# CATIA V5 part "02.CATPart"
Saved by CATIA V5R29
Part number: 02
Bounding box of the stored display mesh (mm): x -24 to 24, y -16 to 0, z 0 to 16
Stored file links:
  F:\1-Dersler\2-BAHAR\Bilgisayar Destekli Mühendislik Tasarımı\montaj2 el mengenesi\02.CATPart
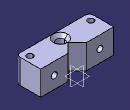
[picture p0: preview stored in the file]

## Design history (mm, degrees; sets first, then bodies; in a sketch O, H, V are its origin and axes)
Body1 (main body)
  Sketch1 on xy-plane, origin (0, 0, 0), H (1, 0, 0), V (0, 1, 0)
    point P1 (-24, 0)
    line L1 (-24, 0) -> (-24, -16)
    line L2 (-24, -16) -> (24, -16)
    line L3 (24, -16) -> (24, 0)
    point P4 (24, 0)
    line L4 (24, 0) -> (6, 0)
    point P5 (6, 0)
    line L5 (6, 0) -> (0, -6)
    point P6 (0, -6)
    line L6 (0, -6) -> (-6, 0)
    point P7 (-6, 0)
    line L7 (-6, 0) -> (-24, 0)
    length L3 = 16
    distance P7 P5 = 12
    length L2 = 48
    coincidence: P1 H, P4 H, P6 V, P7 H
    vertical: L1 V, L3 V
    horizontal: L2 H, L4 H, L7 H
    symmetry: L5 L6 V, L3 L1 V
    perpendicularity: L5 L6
  Pad1: profile Sketch1, direction (0, 0, 1), length 16
  Fillet1: radius 2.5, on edge [face of Pad1 from Sketch1.L3 | face of Pad1 from Sketch1.L2]; edge [face of Pad1 from Sketch1.L2 | face of Pad1 from Sketch1.L1]
  Sketch2 on end face of Pad1, origin (-2.7315, -10.8384, 16), H (1, 0, 0), V (0, 1, 0)
    point P1 (2.7315, -0.1616)
    reference intersected line E1 through (2.7315, 0) direction (0, 1) from yz-plane
    reference projected line E2 (-21.2685, -5.1616) -> (26.7315, -5.1616) from edge [face of Pad1 from Sketch1.L2 | end face of Pad1]
    distance P1 E2 = 5
    coincidence: P1 E1
  Hole1: placed by Sketch2, at (0, -11, 16) direction (0, 0, -1), diameter 5.5, through (limit type 6), countersink depth 2, countersink angle 90
  Sketch3 on end face of Pad1, origin (20.0862, -12.7659, 16), H (1, 0, 0), V (0, 1, 0)
    point P1 (-0.0862, 1.7659)
    reference projected line E1 (-44.0862, -3.2341) -> (3.9138, -3.2341) from edge [face of Pad1 from Sketch1.L2 | end face of Pad1]
    reference intersected line E2 through (-20.0862, 0) direction (0, 1) from yz-plane
    distance P1 E1 = 5
    distance P1 E2 = 20
  Hole2: placed by Sketch3, at (20, -11, 16) direction (0, 0, -1), diameter 4, through (limit type 6)
  Mirror1: of Hole2, about yz-plane
  Sketch4 on face of Pad1 from Sketch1.L4, origin (15.1194, 0, 9.3485), H (1, 0, 0), V (0, 0, -1)
    point P1 (-0.1194, 1.3485)
    reference projected line E1 (8.8806, 9.3485) -> (-9.1194, 9.3485) from edge [start face of Pad1 | face of Pad1 from Sketch1.L4]
    reference intersected line E2 through (-15.1194, 0) direction (0, 1) from yz-plane
    distance E1 P1 = 8
    distance P1 E2 = 15
  Hole3: placed by Sketch4, at (15, 0, 8) direction (0, -1, 0), diameter 4, through (limit type 6)
  Mirror2: of Hole3, about yz-plane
